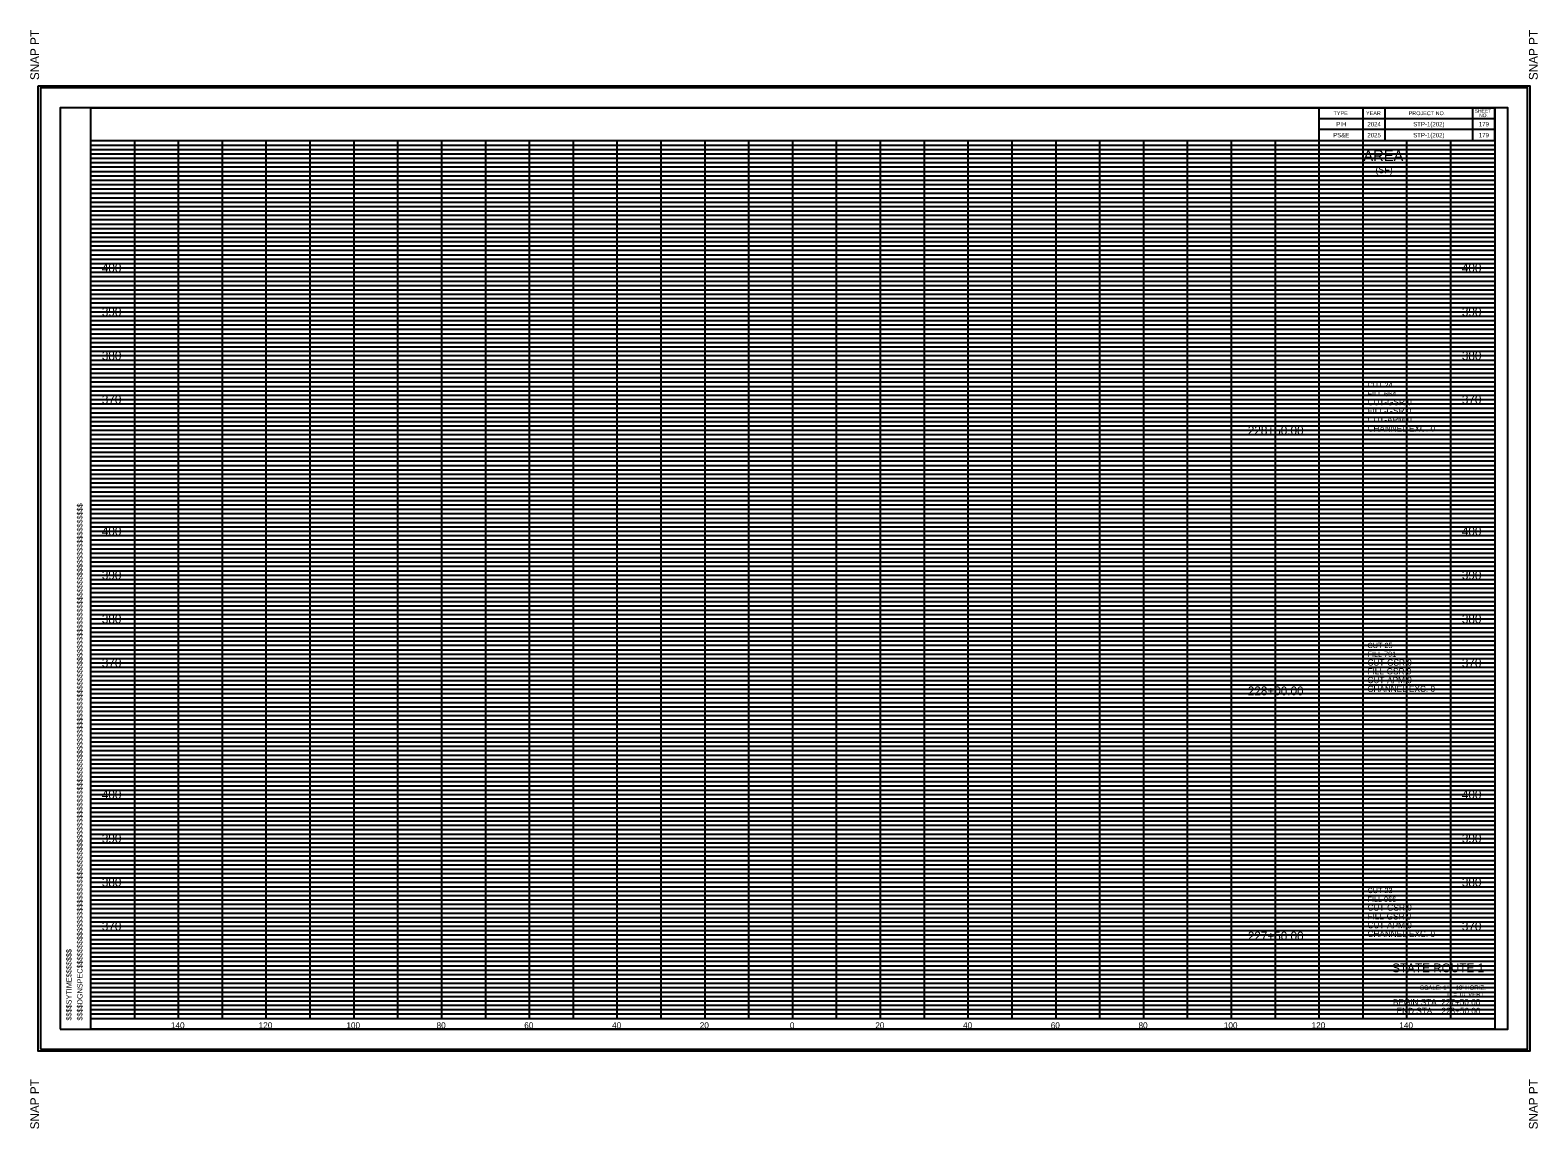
# Model space of a CAD drawing. Extents: x -200 to 23470, y -200 to 2389.
# Drawn here: x 9326.2 to 9669.8, y 2014.8 to 2265.2 of the extents above; entities that cross this region are included whole.
import ezdxf

# ---------------------------------------------------------------- set-up
doc = ezdxf.new("R2010")
doc.units = 0
for name, color, linetype in [('Default', 7, 'Continuous'), ('DESIGN - SCRATCH - User 1', 7, 'Continuous'), ('DESIGN - SCRATCH - User 2', 7, 'Continuous'), ('DESIGN - SHEET - Corner Text', 7, 'Continuous'), ('DESIGN - SHEET - Light Grid', 7, 'Continuous'), ('DESIGN - SHEET - Linework', 7, 'Continuous'), ('DESIGN - SHEET - Plot Shape', 7, 'Continuous'), ('DESIGN - TYPICAL - Text', 7, 'Continuous'), ('SURVEY - CENTERLINE - Preliminary', 7, 'Continuous')]:
    doc.layers.add(name, color=color, linetype=linetype)

# ---------------------------------------------------------------- blocks, each defined once
blk = doc.blocks.new('XSTSHT')
at = {"layer": 'DESIGN - SCRATCH - User 1'}
for p, q in [((28.5, 20.375), (28.5, 20.375)), ((29.25, 20.375), (29.25, 20.375)), ((30.5, 20.375), (30.5, 20.375)), ((31.75, 20.375), (31.75, 20.375)), ((28.5, 20.125), (28.5, 20.125)), ((29.25, 20.125), (29.25, 20.125)), ((30.5, 20.125), (30.5, 20.125)), ((31.75, 20.125), (31.75, 20.125)), ((0, 0), (0, 0))]:
    blk.add_line(p, q, dxfattribs=at)
at = {"layer": 'DESIGN - SHEET - Light Grid'}
for p, q in [((0, 19.9), (32, 19.9)), ((0, 19.8), (32, 19.8)), ((0, 19.7), (32, 19.7)), ((0, 19.6), (32, 19.6)), ((0, 19.5), (32, 19.5)), ((0, 19.4), (32, 19.4)), ((0, 19.3), (32, 19.3)), ((0, 19.2), (32, 19.2)), ((0, 19.1), (32, 19.1)), ((0, 18.9), (32, 18.9)), ((0, 18.8), (32, 18.8)), ((0, 18.7), (32, 18.7)), ((0, 18.6), (32, 18.6)), ((0, 18.5), (32, 18.5)), ((0, 18.4), (32, 18.4)), ((0, 18.3), (32, 18.3)), ((0, 18.2), (32, 18.2)), ((0, 18.1), (32, 18.1)), ((0, 17.9), (32, 17.9)), ((0, 17.8), (32, 17.8)), ((0, 17.7), (32, 17.7)), ((0, 17.6), (32, 17.6)), ((0, 17.5), (32, 17.5)), ((0, 17.4), (32, 17.4)), ((0, 17.3), (32, 17.3)), ((0, 17.2), (32, 17.2)), ((0, 17.1), (32, 17.1)), ((0, 16.9), (32, 16.9)), ((0, 16.8), (32, 16.8)), ((0, 16.7), (32, 16.7)), ((0, 16.6), (32, 16.6)), ((0, 16.5), (32, 16.5)), ((0, 16.4), (32, 16.4)), ((0, 16.3), (32, 16.3)), ((0, 16.2), (32, 16.2)), ((0, 16.1), (32, 16.1)), ((0, 15.9), (32, 15.9)), ((0, 15.8), (32, 15.8)), ((0, 15.7), (32, 15.7)), ((0, 15.6), (32, 15.6)), ((0, 15.5), (32, 15.5)), ((0, 15.4), (32, 15.4)), ((0, 15.3), (32, 15.3)), ((0, 15.2), (32, 15.2)), ((0, 15.1), (32, 15.1)), ((0, 14.9), (32, 14.9)), ((0, 14.8), (32, 14.8)), ((0, 14.7), (32, 14.7)), ((0, 14.6), (32, 14.6)), ((0, 14.5), (32, 14.5)), ((0, 14.4), (32, 14.4)), ((0, 14.3), (32, 14.3)), ((0, 14.2), (32, 14.2)), ((0, 14.1), (32, 14.1)), ((0, 13.9), (32, 13.9)), ((0, 13.8), (32, 13.8)), ((0, 13.7), (32, 13.7)), ((0, 13.6), (32, 13.6)), ((0, 13.5), (32, 13.5)), ((0, 13.4), (32, 13.4)), ((0, 13.3), (32, 13.3)), ((0, 13.2), (32, 13.2)), ((0, 13.1), (32, 13.1)), ((0, 12.9), (32, 12.9)), ((0, 12.8), (32, 12.8)), ((0, 12.7), (32, 12.7)), ((0, 12.6), (32, 12.6)), ((0, 12.5), (32, 12.5)), ((0, 12.4), (32, 12.4)), ((0, 12.3), (32, 12.3)), ((0, 12.2), (32, 12.2)), ((0, 12.1), (32, 12.1)), ((0, 11.9), (32, 11.9)), ((0, 11.8), (32, 11.8)), ((0, 11.7), (32, 11.7)), ((0, 11.6), (32, 11.6)), ((0, 11.5), (32, 11.5)), ((0, 11.4), (32, 11.4)), ((0, 11.3), (32, 11.3)), ((0, 11.2), (32, 11.2)), ((0, 11.1), (32, 11.1)), ((0, 10.9), (32, 10.9)), ((0, 10.8), (32, 10.8)), ((0, 10.7), (32, 10.7)), ((0, 10.6), (32, 10.6)), ((0, 10.5), (32, 10.5)), ((0, 10.4), (32, 10.4)), ((0, 10.3), (32, 10.3)), ((0, 10.2), (32, 10.2)), ((0, 10.1), (32, 10.1)), ((0, 9.9), (32, 9.9)), ((0, 9.8), (32, 9.8)), ((0, 9.7), (32, 9.7)), ((0, 9.6), (32, 9.6)), ((0, 9.5), (32, 9.5)), ((0, 9.4), (32, 9.4)), ((0, 9.3), (32, 9.3)), ((0, 9.2), (32, 9.2)), ((0, 9.1), (32, 9.1)), ((0, 8.9), (32, 8.9)), ((0, 8.8), (32, 8.8)), ((0, 8.7), (32, 8.7)), ((0, 8.6), (32, 8.6)), ((0, 8.5), (32, 8.5)), ((0, 8.4), (32, 8.4)), ((0, 8.3), (32, 8.3)), ((0, 8.2), (32, 8.2)), ((0, 8.1), (32, 8.1)), ((0, 7.9), (32, 7.9)), ((0, 7.8), (32, 7.8)), ((0, 7.7), (32, 7.7)), ((0, 7.6), (32, 7.6)), ((0, 7.5), (32, 7.5)), ((0, 7.4), (32, 7.4)), ((0, 7.3), (32, 7.3)), ((0, 7.2), (32, 7.2)), ((0, 7.1), (32, 7.1)), ((0, 6.9), (32, 6.9)), ((0, 6.8), (32, 6.8)), ((0, 6.7), (32, 6.7)), ((0, 6.6), (32, 6.6)), ((0, 6.5), (32, 6.5)), ((0, 6.4), (32, 6.4)), ((0, 6.3), (32, 6.3)), ((0, 6.2), (32, 6.2)), ((0, 6.1), (32, 6.1)), ((0, 5.9), (32, 5.9)), ((0, 5.8), (32, 5.8)), ((0, 5.7), (32, 5.7)), ((0, 5.6), (32, 5.6)), ((0, 5.5), (32, 5.5)), ((0, 5.4), (32, 5.4)), ((0, 5.3), (32, 5.3)), ((0, 5.2), (32, 5.2)), ((0, 5.1), (32, 5.1)), ((0, 4.9), (32, 4.9)), ((0, 4.8), (32, 4.8)), ((0, 4.7), (32, 4.7)), ((0, 4.6), (32, 4.6)), ((0, 4.5), (32, 4.5)), ((0, 4.4), (32, 4.4)), ((0, 4.3), (32, 4.3)), ((0, 4.2), (32, 4.2)), ((0, 4.1), (32, 4.1)), ((0, 3.9), (32, 3.9)), ((0, 3.8), (32, 3.8)), ((0, 3.7), (32, 3.7)), ((0, 3.6), (32, 3.6)), ((0, 3.5), (32, 3.5)), ((0, 3.4), (32, 3.4)), ((0, 3.3), (32, 3.3)), ((0, 3.2), (32, 3.2)), ((0, 3.1), (32, 3.1)), ((0, 2.9), (32, 2.9)), ((0, 2.8), (32, 2.8)), ((0, 2.7), (32, 2.7)), ((0, 2.6), (32, 2.6)), ((0, 2.5), (32, 2.5)), ((0, 2.4), (32, 2.4)), ((0, 2.3), (32, 2.3)), ((0, 2.2), (32, 2.2)), ((0, 2.1), (32, 2.1)), ((0, 1.9), (32, 1.9)), ((0, 1.8), (32, 1.8)), ((0, 1.7), (32, 1.7)), ((0, 1.6), (32, 1.6)), ((0, 1.5), (32, 1.5)), ((0, 1.4), (32, 1.4)), ((0, 1.3), (32, 1.3)), ((0, 1.2), (32, 1.2)), ((0, 1.1), (32, 1.1)), ((0, 0.9), (32, 0.9)), ((0, 0.8), (32, 0.8)), ((0, 0.7), (32, 0.7)), ((0, 0.6), (32, 0.6)), ((0, 0.5), (32, 0.5)), ((0, 0.4), (32, 0.4)), ((0, 0.3), (32, 0.3)), ((0, 0.2), (32, 0.2)), ((0, 0.1), (32, 0.1))]:
    blk.add_line(p, q, dxfattribs=at)
at = {"layer": 'DESIGN - SHEET - Linework'}
for p, q in [((32, 20.75), (28, 20.75)), ((28, 20), (28, 20.75)), ((29, 20), (29, 20.75)), ((29.5, 20), (29.5, 20.75)), ((31.5, 20), (31.5, 20.75)), ((32, 20), (32, 20.75)), ((32, 20.5), (28, 20.5)), ((0, 20), (32, 20)), ((1, 0), (1, 20)), ((2, 0), (2, 20)), ((3, 0), (3, 20)), ((4, 0), (4, 20)), ((5, 0), (5, 20)), ((6, 0), (6, 20)), ((7, 0), (7, 20)), ((8, 0), (8, 20)), ((9, 0), (9, 20)), ((10, 0), (10, 20)), ((11, 0), (11, 20)), ((12, 0), (12, 20)), ((13, 0), (13, 20)), ((14, 0), (14, 20)), ((15, 0), (15, 20)), ((16, 0), (16, 20)), ((17, 0), (17, 20)), ((18, 0), (18, 20)), ((19, 0), (19, 20)), ((20, 0), (20, 20)), ((21, 0), (21, 20)), ((22, 0), (22, 20)), ((23, 0), (23, 20)), ((24, 0), (24, 20)), ((25, 0), (25, 20)), ((26, 0), (26, 20)), ((27, 0), (27, 20)), ((32, 20.25), (28, 20.25)), ((28, 0), (28, 20)), ((29, 0), (29, 20)), ((30, 0), (30, 20)), ((31, 0), (31, 20)), ((0, 19), (32, 19)), ((0, 18), (32, 18)), ((0, 17), (32, 17)), ((0, 16), (32, 16)), ((0, 15), (32, 15)), ((0, 14), (32, 14)), ((0, 13), (32, 13)), ((0, 12), (32, 12)), ((0, 11), (32, 11)), ((0, 10), (32, 10)), ((0, 9), (32, 9)), ((0, 8), (32, 8)), ((0, 7), (32, 7)), ((0, 6), (32, 6)), ((0, 5), (32, 5)), ((0, 4), (32, 4)), ((0, 3), (32, 3)), ((0, 2), (32, 2)), ((0, 1), (32, 1)), ((0, 0), (32, 0))]:
    blk.add_line(p, q, dxfattribs=at)
for points in [[(-1.2, 21.25), (32.8, 21.25), (32.8, -0.75), (-1.2, -0.75)], [(0, 20.75), (32, 20.75), (32, -0.25), (0, -0.25)]]:
    blk.add_lwpolyline(points, close=True, dxfattribs=at)
at = {"layer": 'DESIGN - SHEET - Corner Text'}
for s, height, p in [('  SNAP PT', 0.2, (-1.18, 21.23)), ('  SNAP PT', 0.2, (32.98, 21.23)), ('$$$$DGNSPEC$$$$$$$$$$$$$$$$$$$$$$$$$$$$$$$$$$$$$$$$$$$$$$$$$$$$$$$$$$$$$$$$$$$$$$$$$$$$$$$$$$$$$$$$$$$$$$$$$$$$$$$$$$$$$$$$$$$', 0.12, (-0.19, -0.05)), ('$$$$SYTIME$$$$$$$', 0.12, (-0.44, -0.05)), ('SNAP PT  ', 0.2, (-1.18, -2.53)), ('SNAP PT  ', 0.2, (32.98, -2.53))]:
    blk.add_text(s, height=height, rotation=90, dxfattribs=at).set_placement(p)
at = {"layer": 'DESIGN - SHEET - Light Grid'}
for s, height, p in [('TYPE', 0.09, (28.326, 20.58)), ('YEAR', 0.09, (29.066, 20.58)), ('PROJECT NO.', 0.09, (30.038, 20.58)), ('SHEET', 0.08, (31.547, 20.635)), ('NO.', 0.08, (31.647, 20.535))]:
    blk.add_text(s, height=height, dxfattribs=at).set_placement(p)

msp = doc.modelspace()

# ---------------------------------------------------------------- linework, layer by layer
at = {"layer": 'DESIGN - SCRATCH - User 2'}
msp.add_line((9590, 2040), (9640, 2040), dxfattribs=at)
at = {"layer": 'DESIGN - SHEET - Plot Shape'}
for points in [[(9328.5, 2033), (9667.5, 2033), (9667.5, 2252), (9328.5, 2252)], [(9333, 2037.5), (9663, 2037.5), (9663, 2247.5), (9333, 2247.5)]]:
    msp.add_lwpolyline(points, close=True, dxfattribs=at)

# ---------------------------------------------------------------- block references
at = {"layer": 'DESIGN - SHEET - Plot Shape', "xscale": 10, "yscale": 10}
msp.add_blockref('XSTSHT', (9340, 2040), dxfattribs=at)
at = {"layer": 'SURVEY - CENTERLINE - Preliminary', "xscale": 10, "yscale": 10}
msp.add_blockref('XSTSHT', (9340, 2040), dxfattribs=at)
msp.add_blockref('XSTSHT', (9340, 2040), dxfattribs=at)

# ---------------------------------------------------------------- texts
at = {"layer": 'Default'}
for s, height, p in [('     400     ', 2, (9338.79, 2210)), ('     400     ', 2, (9648.79, 2210)), ('     390     ', 2, (9338.79, 2200)), ('     390     ', 2, (9648.79, 2200)), ('     380     ', 2, (9338.79, 2190)), ('     380     ', 2, (9648.79, 2190)), ('     370     ', 2, (9338.79, 2180)), ('     370     ', 2, (9648.79, 2180)), ('     228+50.00     ', 2, (9600, 2172.96)), ('     400     ', 2, (9338.79, 2150)), ('     400     ', 2, (9648.79, 2150)), ('     390     ', 2, (9338.79, 2140)), ('     390     ', 2, (9648.79, 2140)), ('     380     ', 2, (9338.79, 2130)), ('     380     ', 2, (9648.79, 2130)), ('     370     ', 2, (9338.79, 2120)), ('     370     ', 2, (9648.79, 2120)), ('     228+00.00     ', 2, (9600, 2113.62)), ('     400     ', 2, (9338.79, 2090)), ('     400     ', 2, (9648.79, 2090)), ('     390     ', 2, (9338.79, 2080)), ('     390     ', 2, (9648.79, 2080)), ('     380     ', 2, (9338.79, 2070)), ('     380     ', 2, (9648.79, 2070)), ('     370     ', 2, (9338.79, 2060)), ('     370     ', 2, (9648.79, 2060)), ('     227+50.00     ', 2, (9600, 2057.76)), ('     140     ', 1.4, (9355.65, 2037.7)), ('     120     ', 1.4, (9375.65, 2037.7)), ('     100     ', 1.4, (9395.65, 2037.7)), ('     80     ', 1.4, (9416.2, 2037.7)), ('     60     ', 1.4, (9436.2, 2037.7)), ('     40     ', 1.4, (9456.2, 2037.7)), ('     20     ', 1.4, (9476.2, 2037.7)), ('     0     ', 1.4, (9496.74, 2037.7)), ('     0     ', 1.4, (9496.74, 2037.7)), ('     20     ', 1.4, (9516.2, 2037.7)), ('     40     ', 1.4, (9536.2, 2037.7)), ('     60     ', 1.4, (9556.2, 2037.7)), ('     80     ', 1.4, (9576.2, 2037.7)), ('     100     ', 1.4, (9595.65, 2037.7)), ('     120     ', 1.4, (9615.65, 2037.7)), ('     140     ', 1.4, (9635.65, 2037.7))]:
    msp.add_text(s, height=height, dxfattribs=at).set_placement(p)
at = {"layer": 'DESIGN - SHEET - Corner Text'}
for s, height, p in [('PIH', 1, (9623.89, 2243.25)), ('2024', 1, (9630.98, 2243.25)), ('STP-1(202)', 1, (9641.42, 2243.25)), ('179', 1, (9656.37, 2243.25)), ('PS&E', 1, (9623.17, 2240.75)), ('2025', 1, (9630.97, 2240.75)), ('STP-1(202)', 1, (9641.42, 2240.75)), ('179', 1, (9656.37, 2240.75)), ('STATE ROUTE 1', 2, (9636.62, 2050.5)), ('SCALE: 1" = 10\' HORIZ.', 1, (9642.96, 2046.5)), ('1" = 10\' VERT.', 1, (9648.93, 2045)), ('BEGIN STA. 227+50.00', 1.4, (9636.78, 2043)), ('END STA.   228+50.00', 1.4, (9637.65, 2041))]:
    msp.add_text(s, height=height, dxfattribs=at).set_placement(p)
at = {"layer": 'DESIGN - TYPICAL - Text'}
for s, height, p in [('AREA', 2.5, (9630.07, 2235.33)), ('(SF)', 1.5, (9632.83, 2232.58)), ('CUT 24', 1.2, (9631, 2183.71)), ('FILL 664', 1.2, (9631, 2181.71)), ('CUT-GSR 0', 1.4, (9631, 2179.71)), ('FILL-GSR 0', 1.4, (9631, 2177.71)), ('CUT-APM 0', 1.4, (9631, 2175.71)), ('CHANNEL EXC. 0', 1.4, (9631, 2173.71)), ('CUT 25', 1.2, (9631, 2124.37)), ('CUT-GSR 0', 1.4, (9631, 2120.37)), ('FILL 791', 1.2, (9631, 2122.37)), ('CUT-APM 0', 1.4, (9631, 2116.37)), ('FILL-GSR 0', 1.4, (9631, 2118.37)), ('CHANNEL EXC. 0', 1.4, (9631, 2114.37)), ('CUT 23', 1.2, (9631, 2068.53)), ('CUT-GSR 0', 1.4, (9631, 2064.53)), ('FILL 966', 1.2, (9631, 2066.53)), ('FILL-GSR 0', 1.4, (9631, 2062.53)), ('CUT-APM 0', 1.4, (9631, 2060.53)), ('CHANNEL EXC. 0', 1.4, (9631, 2058.53))]:
    msp.add_text(s, height=height, dxfattribs=at).set_placement(p)

doc.saveas('drawing.dxf')
